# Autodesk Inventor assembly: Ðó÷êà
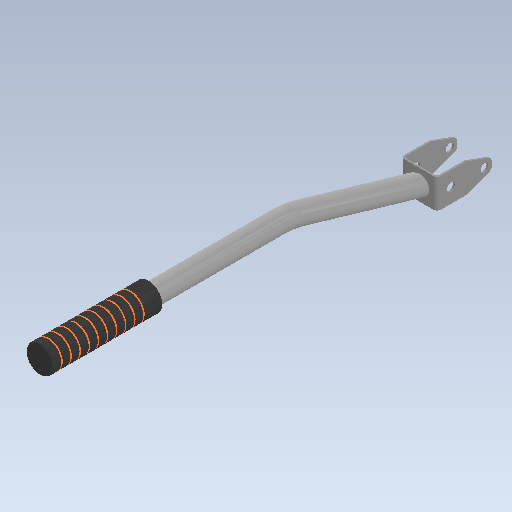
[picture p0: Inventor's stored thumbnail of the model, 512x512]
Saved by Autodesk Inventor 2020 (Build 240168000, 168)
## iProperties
Created: 1900-01
Part Number: Ðó÷êà
Document SubType Name: Assembly
Designer: bruno
Author: bruno
Revision Number: ANYUNSPECIFIED
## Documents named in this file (4)
- C:\Users\bruno\Documents\1-Cours-2022-23\1SI\2. Cinématique\Hoverboard\Inventor-Hoverboard\Poignee-1.iam
- C:\Users\bruno\Documents\1-Cours-2022-23\1SI\2. Cinématique\Hoverboard\Inventor-Hoverboard\Poignee.ipt
- C:\Users\bruno\Documents\1-Cours-2022-23\1SI\2. Cinématique\Hoverboard\Inventor-Hoverboard\Chape-1.ipt
- C:\Users\bruno\Documents\1-Cours-2022-23\1SI\2. Cinématique\Hoverboard\Inventor-Hoverboard\HANDLE GRIP_1.ipt
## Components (3 placed, 3 different names)
1. 25
2. 26
3. 27
